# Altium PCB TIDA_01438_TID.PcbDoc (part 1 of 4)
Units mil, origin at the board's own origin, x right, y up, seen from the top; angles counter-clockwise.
Board outline 6250 x 2150 mil, 4 copper layers (Top Layer, V-, V+, Bottom Layer), stack 61.6 mil thick; 360 components, 217 nets, 1141 pads, 401 vias.
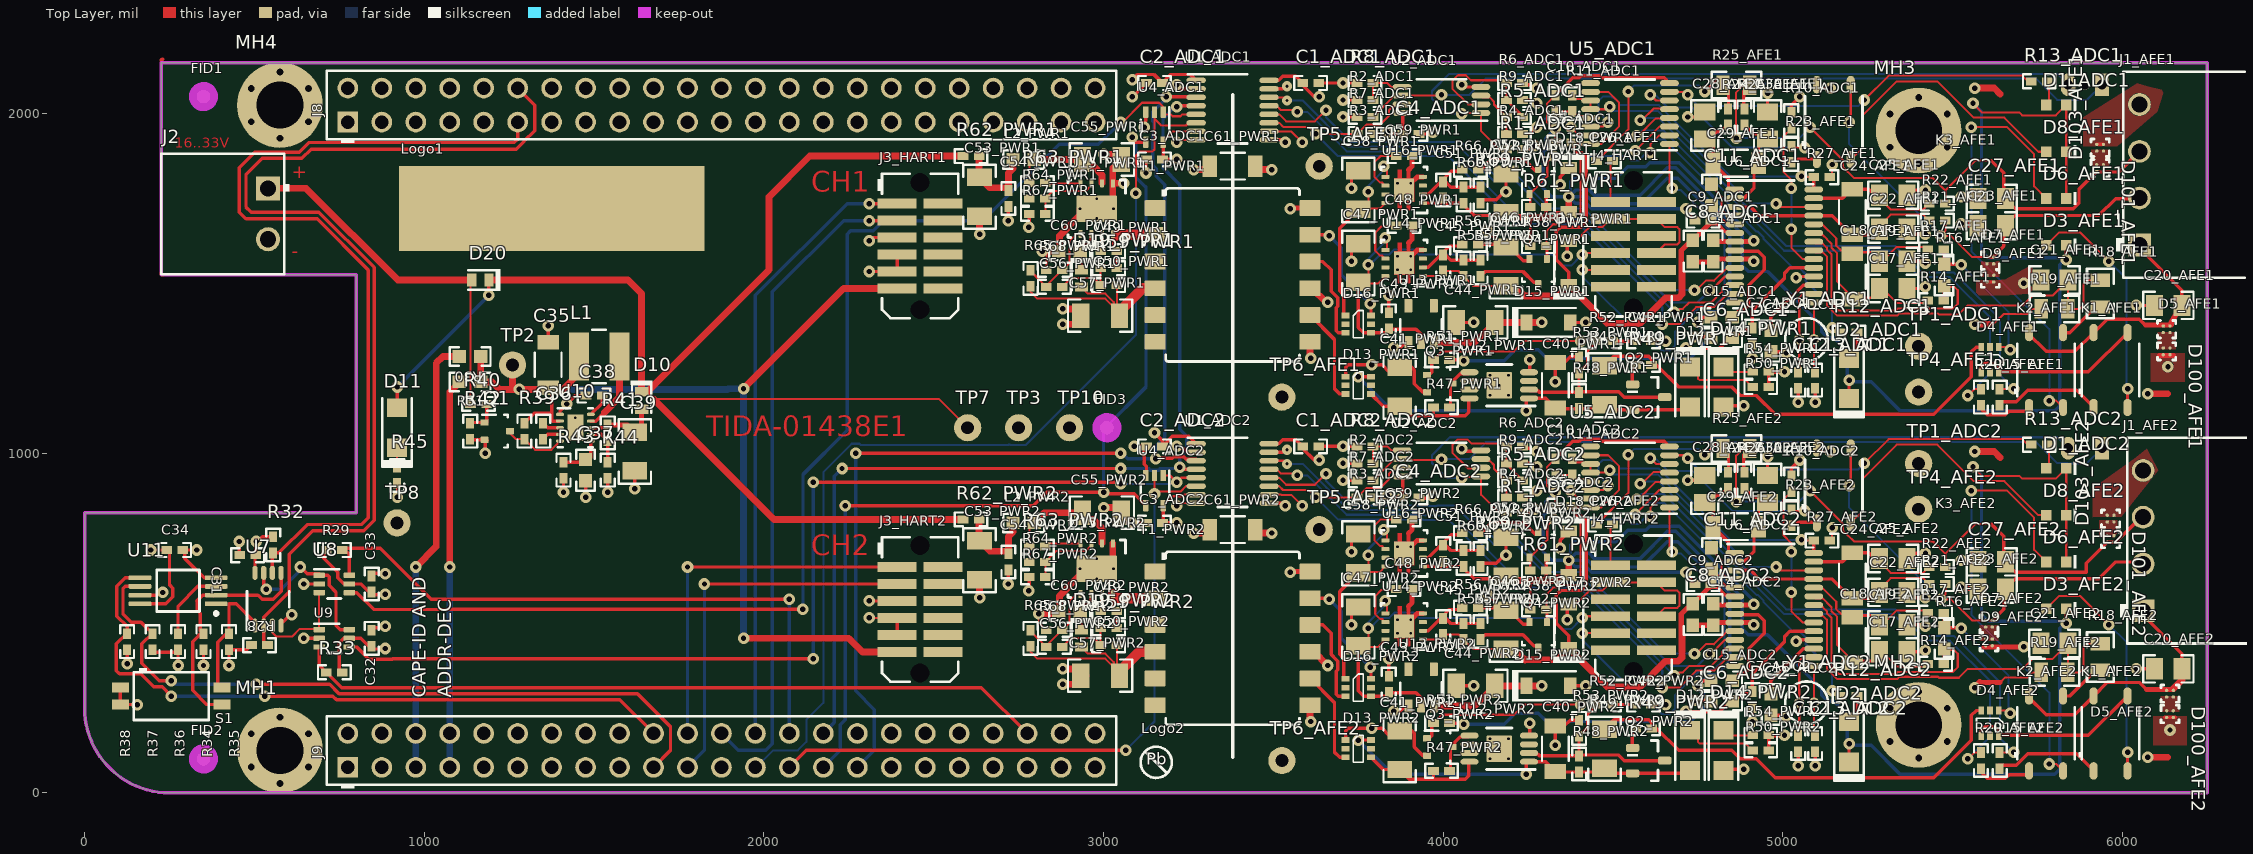
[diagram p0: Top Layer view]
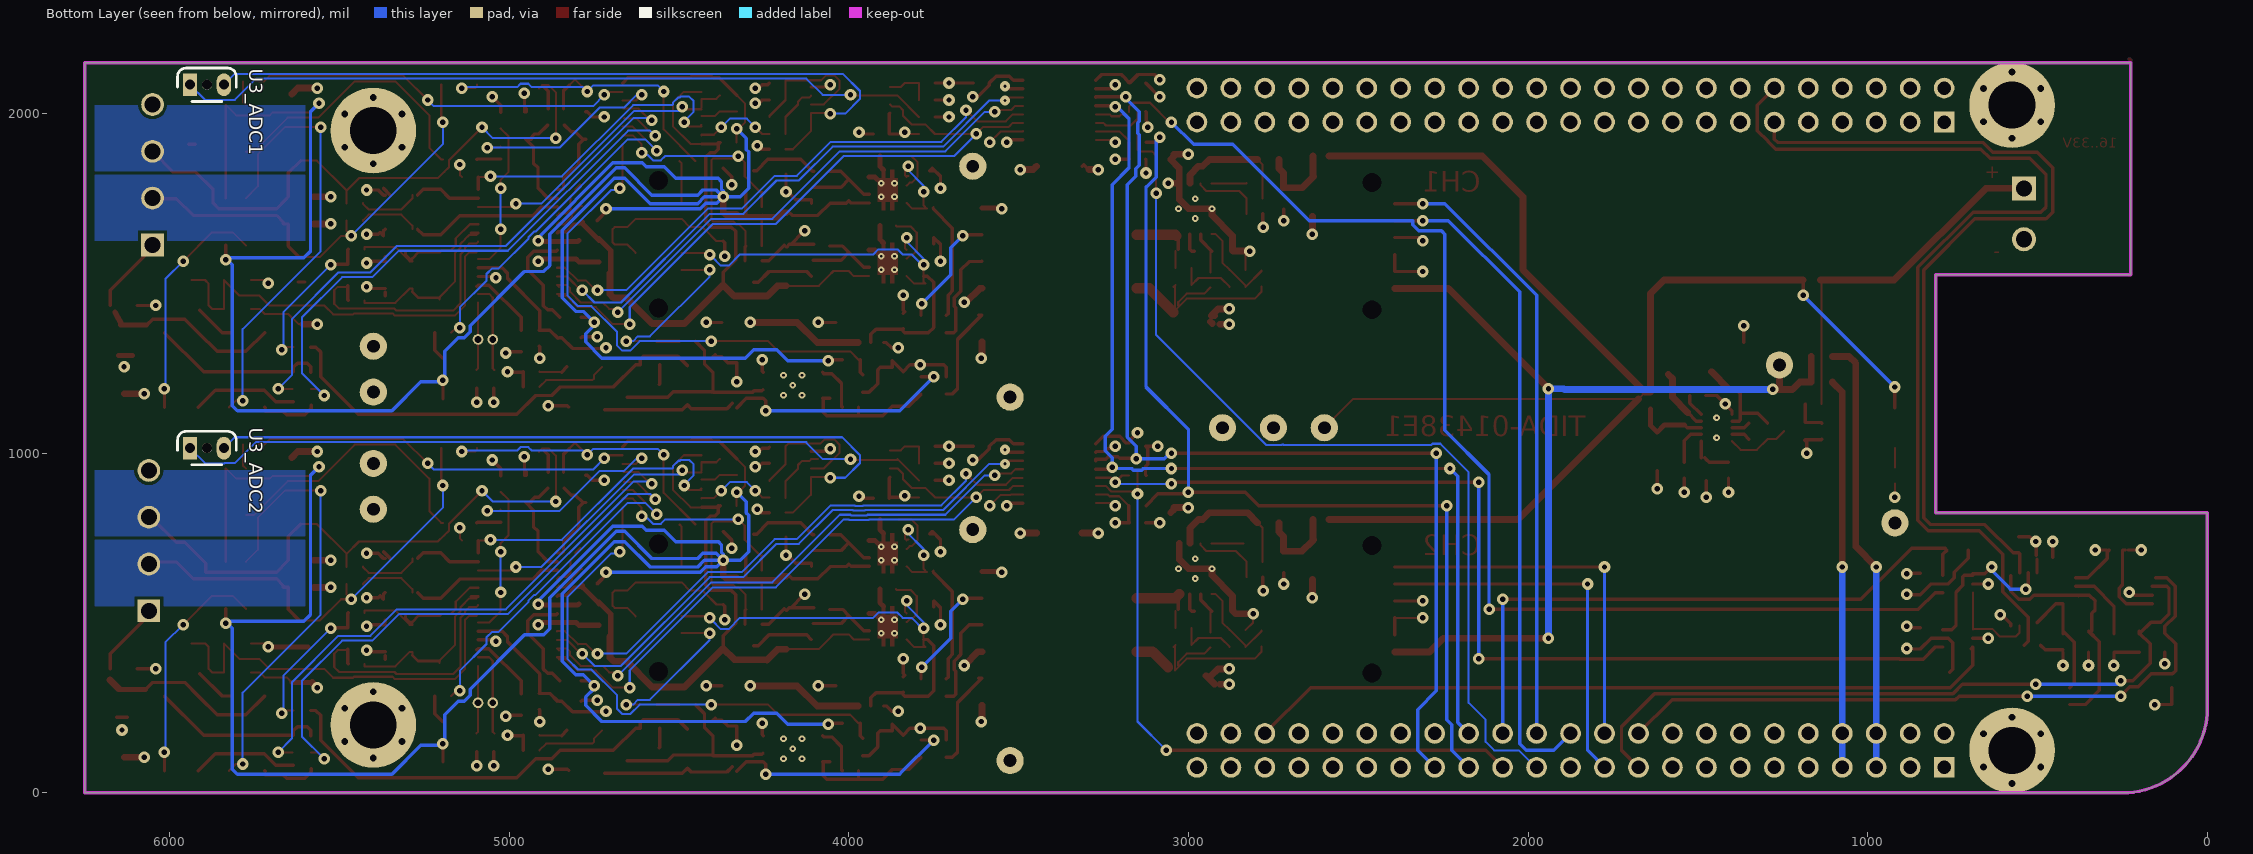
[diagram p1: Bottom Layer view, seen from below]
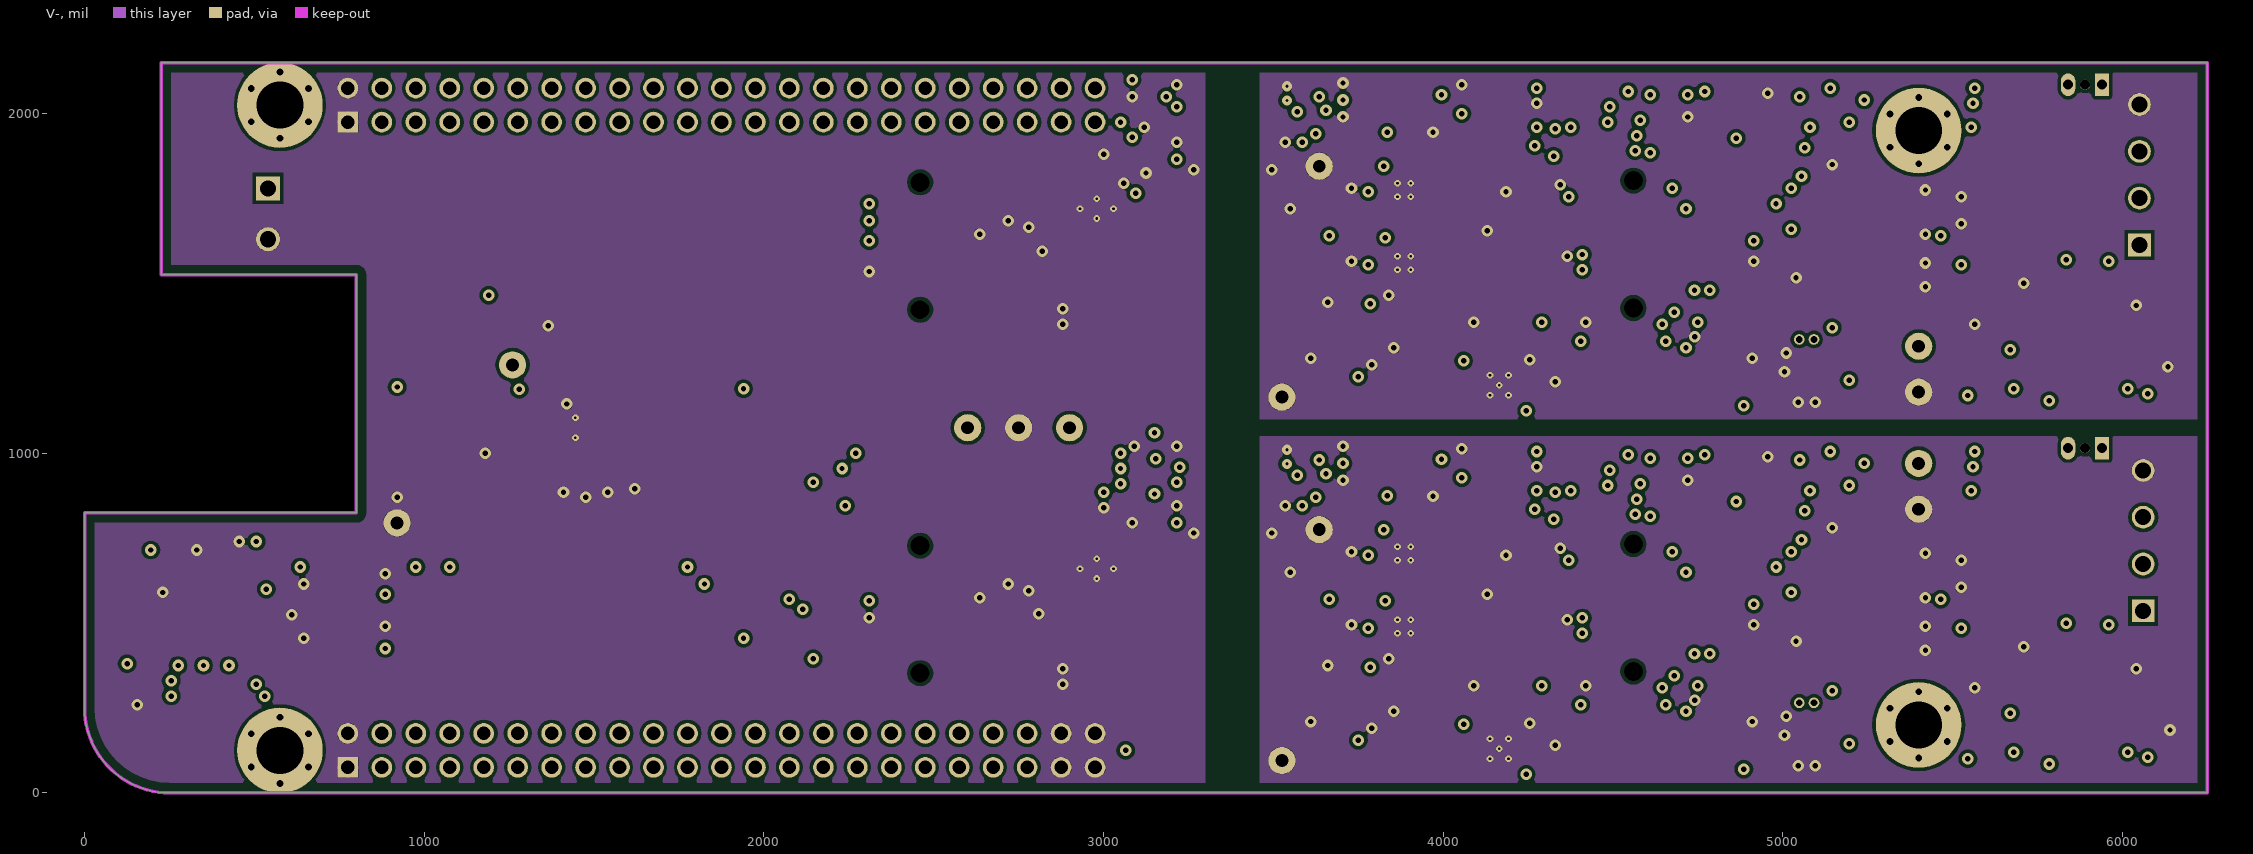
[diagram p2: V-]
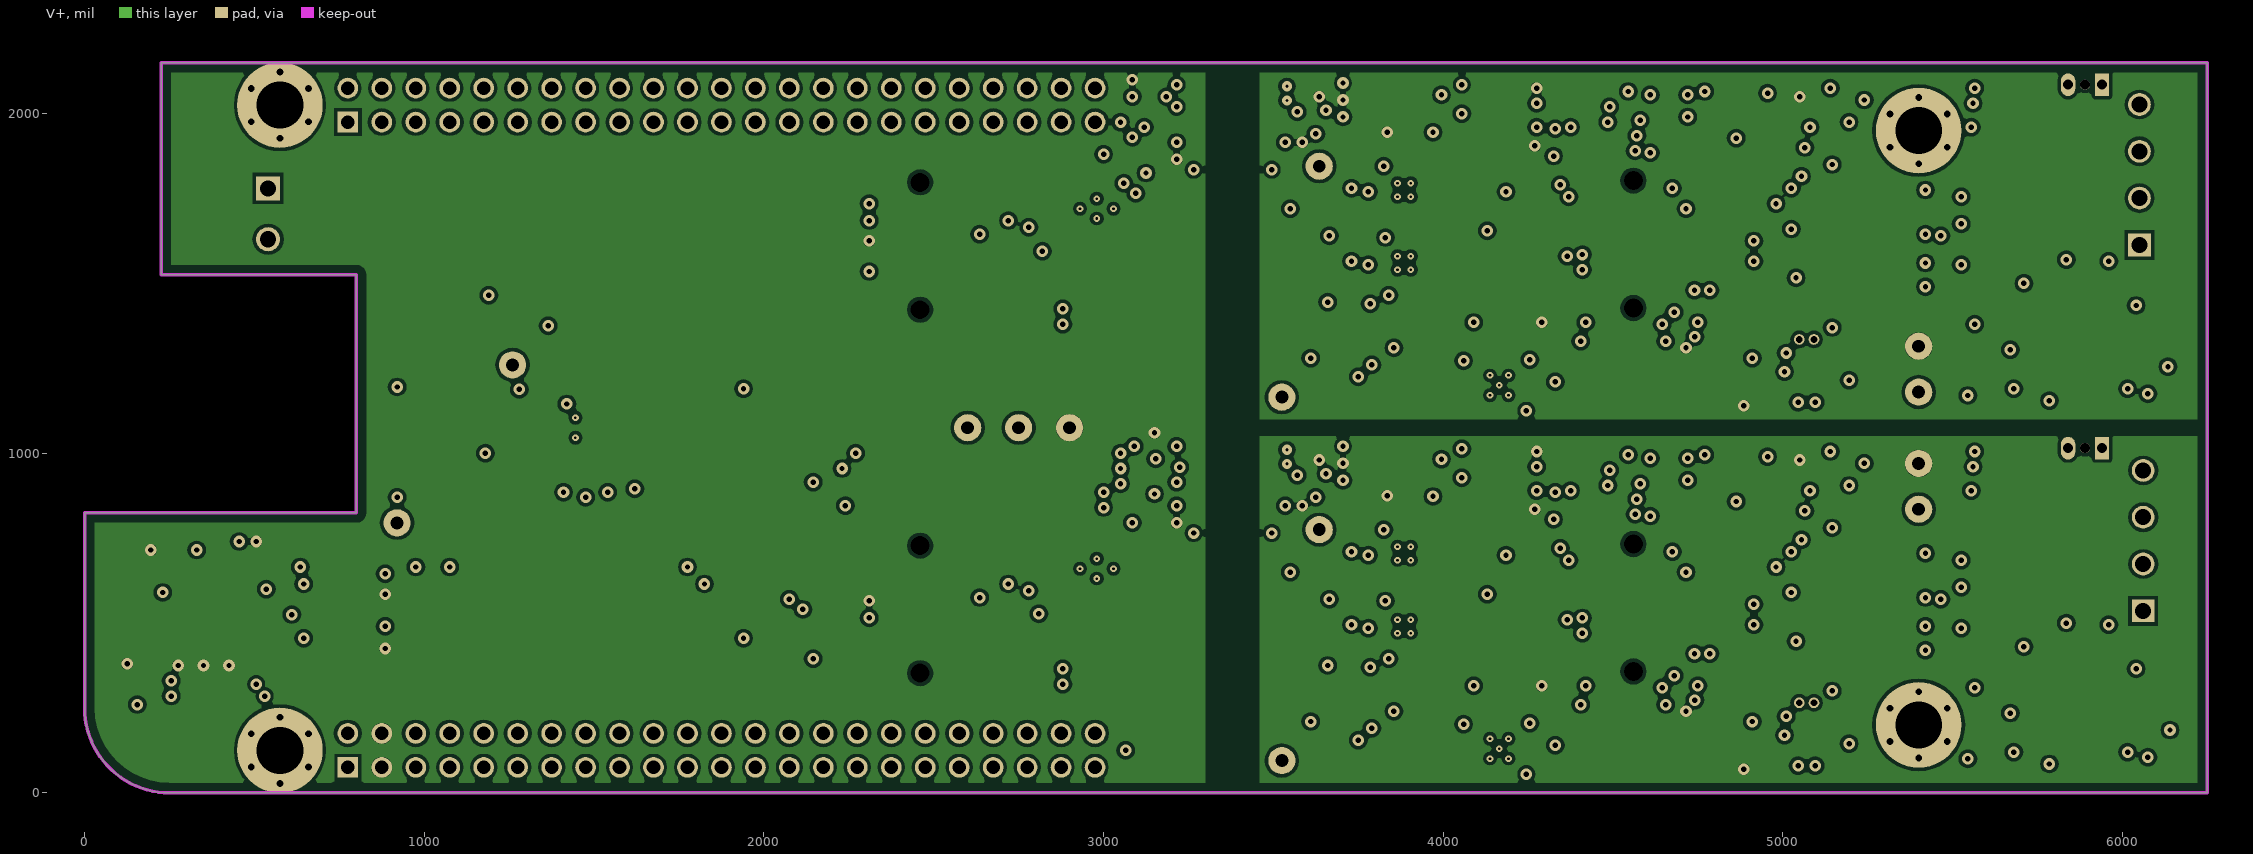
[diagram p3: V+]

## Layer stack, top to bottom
Top Solder: solder mask 0.4, Solder Resist, Dk 3.5
Top Layer: signal copper 1.4
Dielectric 1: core 8, Dk 4.2
V-: signal copper 1.4
Dielectric 2: prepreg 40, FR-4, Dk 4.2
V+: signal copper 1.4
Dielectric 3: core 8, Dk 4.2
Bottom Layer: signal copper 1.4
Bottom Solder: solder mask 0.4, Solder Resist, Dk 3.5

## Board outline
0,250 0,825 800,825 800,1525 225,1525 225,2150 6250,2150 6250,0 250,0 cw(c250,250)

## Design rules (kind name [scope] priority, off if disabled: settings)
AcuteAngle [All] p1: minimum=4.50000000000000E+0001 checktracksonly=FALSE
AssemblyTestPointUsage [All] p1: valid=2
Clearance Clearance_Keepouts [((IsTrack Or IsArc) And Not InPoly) And IsFree and IsKeepOut vs ((IsTrack Or IsArc) And Not InPoly) And IsFree and IsKeepOut] p1: gap=0
Clearance Clearance_BoardEdge_MountingHoles [OnCopper and InComponentClass('Mounting Holes') vs IsKeepOut] p2: gap=40
Clearance Clearance_BoardEdge_Poly [OnCopper and InPoly vs IsKeepOut] p3: gap=25
Clearance Clearance_BoardEdge [OnCopper and Not InComponentClass('Logo') and not InComponentClass('FiducialMark') and not InRegion(1000,500,4000,800) and Not IsKeepout vs IsKeepOut] p4: gap=25
Clearance Clearance_Poly [InPolygon] p5: gap=10
Clearance [All] p6: gap=7.87
ComponentClearance ComponentClearance_Standoff [InComponentClass('U_TIDA_01438_TID_Hardware')] p1: gap=0 collisioncheckmode=3 verticalgap=0 showdistances=FALSE
ComponentClearance ComponentClearance_J2 [InComponent('J2')] p2: gap=0 collisioncheckmode=3 verticalgap=0 showdistances=FALSE
ComponentClearance ComponentClearance_MountingHoles_FiducialMarks [InComponentClass('Mounting Holes') vs InComponentClass('FiducialMark')] p3: gap=50 collisioncheckmode=3 verticalgap=10 showdistances=FALSE
ComponentClearance ComponentClearance_Shunt [InComponentClass('Header') vs InComponentClass('Shunt')] p4: gap=0 collisioncheckmode=3 verticalgap=0 showdistances=FALSE
ComponentClearance ComponentClearance_Logo [InComponentClass('Logo')] p5: gap=50 collisioncheckmode=3 verticalgap=10 showdistances=FALSE
ComponentClearance ComponentClearance_ScrewToNut [(HasFootprint('NY PMS 440 0025 PH')) vs (HasFootprint('Keystone_1902C'))] p6: gap=5 collisioncheckmode=3 verticalgap=10 showdistances=FALSE
ComponentClearance ComponentClearance_MountingHoles [InComponentClass('Mounting Holes')] p7: gap=250 collisioncheckmode=3 verticalgap=100000 showdistances=FALSE
ComponentClearance ComponentClearance_SmallPassives [HasFootprint('0201*') or HasFootprint('0402*') or HasFootprint('0508') or HasFootprint('0603*') or HasFootprint('0612') or HasFootprint('0805*') or HasFootprint('0815*') or HasFootprint('0830*') or HasFootprint('1206*') or HasFootprint('1210*') or HasFootprint('1808*') or HasFootprint('1812*') or HasFootprint('1825*') or HasFootprint('2010*') or HasFootprint('2220*') or HasFootprint('2225*') or HasFootprint('2512*') or HasFootprint('2728*') or HasFootprint('3518*') vs HasFootprint('0201*') or HasFootprint('0402*') or HasFootprint('0508') or HasFootprint('0603*') or HasFootprint('0612') or HasFootprint('0805*') or HasFootprint('0815*') or HasFootprint('0830*') or HasFootprint('1206*') or HasFootprint('1210*') or HasFootprint('1808*') or HasFootprint('1812*') or HasFootprint('1825*') or HasFootprint('2010*') or HasFootprint('2220*') or HasFootprint('2225*') or HasFootprint('2512*') or HasFootprint('2728*') or HasFootprint('3518*')] p8: gap=20 collisioncheckmode=3 verticalgap=10 showdistances=FALSE
ComponentClearance ComponentClearance_THtoSMT [IsThruComponent vs IsSMTComponent] p9: gap=20 collisioncheckmode=3 verticalgap=30 showdistances=FALSE
ComponentClearance ComponentClearance_THtoTH [IsThruComponent vs IsThruComponent] p10: gap=50 collisioncheckmode=3 verticalgap=20 showdistances=FALSE
ComponentClearance [All] p11: gap=10 collisioncheckmode=3 verticalgap=10 showdistances=FALSE
DiffPairsRouting [All] p1: maxlimit=100 minlimit=10 mostfreqgap=10 toplayer_minwidth=15 toplayer_maxwidth=15 toplayer_prefwidth=15 midlayer1_minwidth=15 midlayer1_maxwidth=15 midlayer1_prefwidth=15 midlayer2_minwidth=15 midlayer2_maxwidth=15 midlayer2_prefwidth=15 bottomlayer_minwidth=15 bottomlayer_maxwidth=15 bottomlayer_prefwidth=15 maxuncoupledlength=1000
FabricationTestPointUsage TestPointUsage [All] p1: valid=2 allowmultiple=FALSE
FabricationTestpoint Testpoint [All] p1: side=3 testpointundercomponent=TRUE minsize=40 maxsize=100 preferedsize=60 minholesize=0 maxholesize=40 preferedholesize=32 testpointgrid=1 allowsidetop=TRUE allowsidebottom=TRUE usegrid=TRUE gridtolerance=0.01
FanoutControl Fanout_LCC [IsLCC] p1: bgadir=Out bgaviamode=Centered fanoutstyle=Auto fanoutdirection=Alternating viagrid=1 // Fanout_LCC (Default Rule)
FanoutControl Fanout_BGA [IsBGA] p2: bgadir=Out bgaviamode=Centered fanoutstyle=Auto fanoutdirection=Alternating viagrid=1 // Fanout_BGA (Default Rule)
FanoutControl Fanout_Default [All] p4: bgadir=Out bgaviamode=Centered fanoutstyle=Auto fanoutdirection=Alternating viagrid=1 // Fanout_Default (Default Rule)
FanoutControl Fanout_Small [(CompPinCount < 5)] p5: bgadir=Out bgaviamode=Centered fanoutstyle=Auto fanoutdirection=OutThenIn viagrid=1 // Fanout_Small (Default Rule)
HoleSize [All] p1: absolutevalues=TRUE maxlimit=251 minlimit=7 maxpercent=80.000 minpercent=20.000
MinimumAnnularRing MinimumAnnularRing_ThermalPadVias [IsVia and InAnyComponent] p1: minimumring=5.91
MinimumAnnularRing [All] p2: minimumring=5
MinimumSolderMaskSliver MinimumSolderMaskSliver_Logo [InComponentClass('Logo') vs InComponentClass('Logo')] p1: minsoldermaskwidth=0.7
MinimumSolderMaskSliver [All] p2: minsoldermaskwidth=3.94
PlaneConnect [All] p1: planeconnectstyle=Direct reliefexpansion=10 reliefentries=4 reliefconductorwidth=10 reliefairgap=10
PolygonConnect PolygonConnect_TVS3300 [HasFootprint('YZF0004-C01')] p1: connectstyle=Direct reliefconductorwidth=10 reliefentries=4 polygonreliefangle="90 Angle" airgapwidth=10
PolygonConnect PolygonConnect_12 [All vs IsNamedPolygon('GND_CH1_AVDD')] p2: connectstyle=Direct reliefconductorwidth=10 reliefentries=4 polygonreliefangle="90 Angle" airgapwidth=10
PolygonConnect PolygonConnect_11 [All vs IsNamedPolygon('GND_CH1_AVSS')] p3: connectstyle=Direct reliefconductorwidth=10 reliefentries=4 polygonreliefangle="90 Angle" airgapwidth=10
PolygonConnect PolygonConnect_10 [All vs IsNamedPolygon('LOCALTEMP_CH2_P')] p4: connectstyle=Direct reliefconductorwidth=10 reliefentries=4 polygonreliefangle="90 Angle" airgapwidth=10
PolygonConnect PolygonConnect_9 [All vs IsNamedPolygon('LOCALTEMP_CH1_P')] p5: connectstyle=Direct reliefconductorwidth=10 reliefentries=4 polygonreliefangle="90 Angle" airgapwidth=10
PolygonConnect PolygonConnect_8 [All vs IsNamedPolygon('LOCALTEMP_CH1_N')] p6: connectstyle=Direct reliefconductorwidth=10 reliefentries=4 polygonreliefangle="90 Angle" airgapwidth=10
PolygonConnect PolygonConnect_7 [All vs IsNamedPolygon('LOCALTEMP_CH2_N')] p7: connectstyle=Direct reliefconductorwidth=10 reliefentries=4 polygonreliefangle="90 Angle" airgapwidth=10
PolygonConnect PolygonConnect_6 [All vs IsNamedPolygon('LOCALTEMP_N')] p8: connectstyle=Direct reliefconductorwidth=10 reliefentries=4 polygonreliefangle="90 Angle" airgapwidth=10
PolygonConnect PolygonConnect_5 [All vs IsNamedPolygon('LOCALTEMP_P')] p9: connectstyle=Direct reliefconductorwidth=10 reliefentries=4 polygonreliefangle="90 Angle" airgapwidth=10
PolygonConnect PolygonConnect_4 [All vs IsNamedPolygon('LOCALTEMP_N')] p10: connectstyle=Direct reliefconductorwidth=10 reliefentries=4 polygonreliefangle="90 Angle" airgapwidth=10
PolygonConnect PolygonConnect_3 [All vs IsNamedPolygon('V--No Net')] p11: connectstyle=Relief reliefconductorwidth=10 reliefentries=4 polygonreliefangle="90 Angle" airgapwidth=10
PolygonConnect PolygonConnect_2 [All vs IsNamedPolygon('Bottom Layer-GND')] p12: connectstyle=Direct reliefconductorwidth=10 reliefentries=4 polygonreliefangle="90 Angle" airgapwidth=10
PolygonConnect PolygonConnect_1 [All vs IsNamedPolygon('Top Layer-No Net')] p13: connectstyle=Relief reliefconductorwidth=10 reliefentries=4 polygonreliefangle="90 Angle" airgapwidth=10
PolygonConnect [All vs IsNamedPolygon('Top Layer-VCC')] p14: connectstyle=Relief reliefconductorwidth=10 reliefentries=4 polygonreliefangle="90 Angle" airgapwidth=10
RoutingVias RoutingVias_Standoff [InNet('No Net')] p1: holewidth=28 width=50 viastyle="Through Hole" minholewidth=0 minwidth=0 maxholewidth=28 maxwidth=50
RoutingVias ThermalPadVias [IsVia and InAnyComponent] p2: holewidth=7.87 width=19.68 viastyle="Through Hole" minholewidth=7.87 minwidth=10 maxholewidth=50 maxwidth=50
RoutingVias [All] p3 off: holewidth=16 width=34 viastyle="Through Hole" minholewidth=7.87 minwidth=26 maxholewidth=40 maxwidth=65
ShortCircuit ShortCircuit_Standoff [IsVia vs IsPad] p1: allowed=TRUE
ShortCircuit [Not IsVia vs Not  IsPad] p2: allowed=FALSE
SilkToBoardRegionClearance [Not ((IsComment or IsDesignator) And (Hide <> 'False')) and not InRegion(1000,500,4000,800)] p1 off:
SilkToSilkClearance SilkToSilkClearance_Pb-FreeLogo [(HasFootprint('Pb-Free_Overlay_Medium') OR HasFootprint('Pb-Free_Overlay_Small')) vs (HasFootprint('Pb-Free_Overlay_Medium') OR HasFootprint('Pb-Free_Overlay_Small'))] p1 off: silktosilkclearance=0
SilkToSilkClearance [All] p2 off: silktosilkclearance=5
SilkToSolderMaskClearance "Silk to Solder Mask Opening" [All] p1 off: minsilkscreentomaskgap=1 clearancetoexposedcopper=FALSE
SolderMaskExpansion [All] p1: expansion=1.97
Width [All] p1: maxlimit=100 minlimit=6 preferedwidth=10 checkconnectedcopper=TRUE
14 further rules are at their usual default settings.

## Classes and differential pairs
channel class TIDA_01438_TID_Power: PWR1 PWR2
channel class TIDA_01438_TID_HART: HART1 HART2
channel class TIDA_01438_TID_Channel: CH1 CH2
channel class TIDA_01438_TID_AFE: AFE1 AFE2
channel class TIDA_01438_TID_ADS1262: ADC1 ADC2
net class LMT01_OUT[1..2]: LMT01_OUT1 LMT01_OUT2
net class UART_TXD[1..2]: UART_TXD1 UART_TXD2
net class UART_RXD[1..2]: UART_RXD1 UART_RXD2
net class SPI_CS[1..2]: SPI_CS1 SPI_CS2
component class U_TIDA_01438_TID_Hardware: FID1 FID2 FID3 Logo1 Logo2 MH1 MH2 MH3 MH4 ZZ1 ZZ2 ZZ3
component class Logo: Logo1
component class HART2: J3_HART2 J4_HART2
component class HART1: J3_HART1 J4_HART1
component class FiducialMark: FID1 FID2 FID3
component class AssemblyNote: ZZ1 ZZ2 ZZ3
component class TIDA_01438_TID_Cape: C31 C32 C33 C34 C35 C36 C37 C38 C39 D10 D11 D20 J2 J8 J9 L1 Q1 R28 R29 R30 R31 R32 R33 R34 R35 R36 R37 R38 R39 R40 R41 R42 R43 R44 R45 S1 TP2 TP3 TP7 TP8 TP10 U7 U8 U9 U10 U11
component class ADC1: C1_ADC1 C2_ADC1 C3_ADC1 C4_ADC1 C5_ADC1 C6_ADC1 C7_ADC1 C8_ADC1 C9_ADC1 C10_ADC1 C11_ADC1 C12_ADC1 C13_ADC1 C14_ADC1 C15_ADC1 C16_ADC1 D1_ADC1 D2_ADC1 R1_ADC1 R2_ADC1 R3_ADC1 R4_ADC1 R5_ADC1 R6_ADC1 R7_ADC1 R8_ADC1 R9_ADC1 R10_ADC1 R11_ADC1 R12_ADC1 R13_ADC1 TP1_ADC1 U1_ADC1 U2_ADC1 U3_ADC1 U4_ADC1 U5_ADC1 U6_ADC1 Y1_ADC1
component class ADC2: C1_ADC2 C2_ADC2 C3_ADC2 C4_ADC2 C5_ADC2 C6_ADC2 C7_ADC2 C8_ADC2 C9_ADC2 C10_ADC2 C11_ADC2 C12_ADC2 C13_ADC2 C14_ADC2 C15_ADC2 C16_ADC2 D1_ADC2 D2_ADC2 R1_ADC2 R2_ADC2 R3_ADC2 R4_ADC2 R5_ADC2 R6_ADC2 R7_ADC2 R8_ADC2 R9_ADC2 R10_ADC2 R11_ADC2 R12_ADC2 R13_ADC2 TP1_ADC2 U1_ADC2 U2_ADC2 U3_ADC2 U4_ADC2 U5_ADC2 U6_ADC2 Y1_ADC2
component class AFE1: C17_AFE1 C18_AFE1 C19_AFE1 C20_AFE1 C21_AFE1 C22_AFE1 C23_AFE1 C24_AFE1 C25_AFE1 C26_AFE1 C27_AFE1 C28_AFE1 C29_AFE1 C30_AFE1 D3_AFE1 D4_AFE1 D5_AFE1 D6_AFE1 D7_AFE1 D8_AFE1 D9_AFE1 D100_AFE1 D101_AFE1 D103_AFE1 J1_AFE1 K1_AFE1 K2_AFE1 K3_AFE1 R14_AFE1 R15_AFE1 R16_AFE1 R17_AFE1 R18_AFE1 R19_AFE1 R20_AFE1 R21_AFE1 R22_AFE1 R23_AFE1 R24_AFE1 R25_AFE1 R26_AFE1 R27_AFE1 TP4_AFE1 TP5_AFE1 TP6_AFE1
component class AFE2: C17_AFE2 C18_AFE2 C19_AFE2 C20_AFE2 C21_AFE2 C22_AFE2 C23_AFE2 C24_AFE2 C25_AFE2 C26_AFE2 C27_AFE2 C28_AFE2 C29_AFE2 C30_AFE2 D3_AFE2 D4_AFE2 D5_AFE2 D6_AFE2 D7_AFE2 D8_AFE2 D9_AFE2 D100_AFE2 D101_AFE2 D103_AFE2 J1_AFE2 K1_AFE2 K2_AFE2 K3_AFE2 R14_AFE2 R15_AFE2 R16_AFE2 R17_AFE2 R18_AFE2 R19_AFE2 R20_AFE2 R21_AFE2 R22_AFE2 R23_AFE2 R24_AFE2 R25_AFE2 R26_AFE2 R27_AFE2 TP4_AFE2 TP5_AFE2 TP6_AFE2
component class PWR1: C40_PWR1 C41_PWR1 C42_PWR1 C43_PWR1 C44_PWR1 C45_PWR1 C46_PWR1 C47_PWR1 C48_PWR1 C49_PWR1 C50_PWR1 C51_PWR1 C52_PWR1 C53_PWR1 C54_PWR1 C55_PWR1 C56_PWR1 C57_PWR1 C58_PWR1 C59_PWR1 C60_PWR1 C61_PWR1 D12_PWR1 D13_PWR1 D14_PWR1 D15_PWR1 D16_PWR1 D17_PWR1 D18_PWR1 D19_PWR1 L2_PWR1 Q2_PWR1 Q3_PWR1 Q4_PWR1 Q5_PWR1 R46_PWR1 R47_PWR1 R48_PWR1 R49_PWR1 R50_PWR1 R51_PWR1 R52_PWR1 R53_PWR1 R54_PWR1 R55_PWR1 R56_PWR1 R57_PWR1 R58_PWR1 R59_PWR1 R60_PWR1 R61_PWR1 R62_PWR1 R63_PWR1 R64_PWR1 R65_PWR1 R66_PWR1 R67_PWR1 R68_PWR1 R69_PWR1 T1_PWR1 U12_PWR1 U13_PWR1 U14_PWR1 U15_PWR1 U16_PWR1
component class PWR2: C40_PWR2 C41_PWR2 C42_PWR2 C43_PWR2 C44_PWR2 C45_PWR2 C46_PWR2 C47_PWR2 C48_PWR2 C49_PWR2 C50_PWR2 C51_PWR2 C52_PWR2 C53_PWR2 C54_PWR2 C55_PWR2 C56_PWR2 C57_PWR2 C58_PWR2 C59_PWR2 C60_PWR2 C61_PWR2 D12_PWR2 D13_PWR2 D14_PWR2 D15_PWR2 D16_PWR2 D17_PWR2 D18_PWR2 D19_PWR2 L2_PWR2 Q2_PWR2 Q3_PWR2 Q4_PWR2 Q5_PWR2 R46_PWR2 R47_PWR2 R48_PWR2 R49_PWR2 R50_PWR2 R51_PWR2 R52_PWR2 R53_PWR2 R54_PWR2 R55_PWR2 R56_PWR2 R57_PWR2 R58_PWR2 R59_PWR2 R60_PWR2 R61_PWR2 R62_PWR2 R63_PWR2 R64_PWR2 R65_PWR2 R66_PWR2 R67_PWR2 R68_PWR2 R69_PWR2 T1_PWR2 U12_PWR2 U13_PWR2 U14_PWR2 U15_PWR2 U16_PWR2

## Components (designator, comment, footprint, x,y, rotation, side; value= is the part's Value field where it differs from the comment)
C1_ADC1 "C1005X7R1H104K" 0402 3610,2090 r0 top (schematic designator C1)
C1_ADC2 "C1005X7R1H104K" 0402 3610,1020 r0 top (schematic designator C1)
C2_ADC1 "C1005X7R1H104K" 0402 3150,2090 r180 top (schematic designator C2)
C2_ADC2 "C1005X7R1H104K" 0402 3150,1020 r180 top (schematic designator C2)
C3_ADC1 "C1005X7R1H104K" 0402 3150,1865 r180 top (schematic designator C3)
C3_ADC2 "C1005X7R1H104K" 0402 3150,795 r180 top (schematic designator C3)
C4_ADC1 "C1005X7R1H104K" 0402 3905,1940 r0 top (schematic designator C4)
C4_ADC2 "C1005X7R1H104K" 0402 3905,870 r0 top (schematic designator C4)
C5_ADC1 "C1005X7R1H104K" 0402 4355,1915 r180 top (schematic designator C5)
C5_ADC2 "C1005X7R1H104K" 0402 4355,845 r180 top (schematic designator C5)
C6_ADC1 "C1608X7R1C105K" 0603 4820,1340 r180 top (schematic designator C6)
C6_ADC2 "C1608X7R1C105K" 0603 4820,270 r180 top (schematic designator C6)
C7_ADC1 "C1005X7R1H104K" 0402 4910,1345 r270 top (schematic designator C7)
C7_ADC2 "C1005X7R1H104K" 0402 4910,275 r270 top (schematic designator C7)
C8_ADC1 "C1608X7R1C105K" 0603 4735,1595 r270 top (schematic designator C8)
C8_ADC2 "C1608X7R1C105K" 0603 4735,525 r270 top (schematic designator C8)
C9_ADC1 "C1005X7R1H104K" 0402 4765,1685 r180 top (schematic designator C9)
C9_ADC2 "C1005X7R1H104K" 0402 4765,615 r180 top (schematic designator C9)
C10_ADC1 "C1005X7R1H104K" 0402 4330,2030 r90 top (schematic designator C10)
C10_ADC2 "C1005X7R1H104K" 0402 4330,960 r90 top (schematic designator C10)
C11_ADC1 "C1608C0G1E472J" 0603 4790,1760 r270 top (schematic designator C11)
C11_ADC2 "C1608C0G1E472J" 0603 4790,690 r270 top (schematic designator C11)
C12_ADC1 "GRM1555C1E330JA01D" 0402 5045,1215 r270 top (schematic designator C12)
C12_ADC2 "GRM1555C1E330JA01D" 0402 5045,145 r270 top (schematic designator C12)
C13_ADC1 "GRM1555C1E330JA01D" 0402 5095,1215 r270 top (schematic designator C13)
C13_ADC2 "GRM1555C1E330JA01D" 0402 5095,145 r270 top (schematic designator C13)
C14_ADC1 "C1608X7R1C105K" 0603 4795,1595 r270 top (schematic designator C14)
C14_ADC2 "C1608X7R1C105K" 0603 4795,525 r270 top (schematic designator C14)
C15_ADC1 "C1608X7R1C105K" 0603 4820,1400 r180 top (schematic designator C15)
C15_ADC2 "C1608X7R1C105K" 0603 4820,330 r180 top (schematic designator C15)
C16_ADC1 "C1608X7R1C105K" 0603 4965,1330 r270 top (schematic designator C16)
C16_ADC2 "C1608X7R1C105K" 0603 4965,260 r270 top (schematic designator C16)
C17_AFE1 "GRM2195C1H822JA01D" 0805_HV 5325,1485 r0 top (schematic designator C17)
C17_AFE2 "GRM2195C1H822JA01D" 0805_HV 5325,415 r0 top (schematic designator C17)
C18_AFE1 "C3216NP01H104J160AA" 1206_190 5205,1520 r90 top (schematic designator C18)
C18_AFE2 "C3216NP01H104J160AA" 1206_190 5205,450 r90 top (schematic designator C18)
C19_AFE1 "GRM2195C1H822JA01D" 0805_HV 5325,1565 r180 top (schematic designator C19)
C19_AFE2 "GRM2195C1H822JA01D" 0805_HV 5325,495 r180 top (schematic designator C19)
C20_AFE1 "08051C103KAT2A" 0805_HV 6135,1435 r180 top (schematic designator C20)
C20_AFE2 "08051C103KAT2A" 0805_HV 6135,365 r180 top (schematic designator C20)
C21_AFE1 "GRM2195C1H562JA01D" 0805_HV 5800,1510 r180 top (schematic designator C21)
C21_AFE2 "GRM2195C1H562JA01D" 0805_HV 5800,440 r180 top (schematic designator C21)
C22_AFE1 "GRM2195C1H822JA01D" 0805_HV 5325,1660 r0 top (schematic designator C22)
C22_AFE2 "GRM2195C1H822JA01D" 0805_HV 5325,590 r0 top (schematic designator C22)
C23_AFE1 "08051C103KAT2A" 0805_HV 5615,1670 r180 top (schematic designator C23)
C23_AFE2 "08051C103KAT2A" 0805_HV 5615,600 r180 top (schematic designator C23)
C24_AFE1 "C3216NP01H104J160AA" 1206_190 5205,1710 r90 top (schematic designator C24)
C24_AFE2 "C3216NP01H104J160AA" 1206_190 5205,640 r90 top (schematic designator C24)
C25_AFE1 "GRM2195C1H822JA01D" 0805_HV 5325,1760 r180 top (schematic designator C25)
C25_AFE2 "GRM2195C1H822JA01D" 0805_HV 5325,690 r180 top (schematic designator C25)
C26_AFE1 "C1005X7R1H104K" 0402 4475,1860 r0 top (schematic designator C26)
C26_AFE2 "C1005X7R1H104K" 0402 4475,790 r0 top (schematic designator C26)
C27_AFE1 "08051C103KAT2A" 0805_HV 5615,1750 r180 top (schematic designator C27)
C27_AFE2 "08051C103KAT2A" 0805_HV 5615,680 r180 top (schematic designator C27)
C28_AFE1 "GRM2195C1H822JA01D" 0805_HV 4770,1965 r90 top (schematic designator C28)
C28_AFE2 "GRM2195C1H822JA01D" 0805_HV 4770,895 r90 top (schematic designator C28)
C29_AFE1 "C3216NP01H104J160AA" 1206_190 4861.57,1853.77 r0 top (schematic designator C29)
C29_AFE2 "C3216NP01H104J160AA" 1206_190 4861.57,783.77 r0 top (schematic designator C29)
C30_AFE1 "GRM2195C1H822JA01D" 0805_HV 4955,1965 r270 top (schematic designator C30)
C30_AFE2 "GRM2195C1H822JA01D" 0805_HV 4955,895 r270 top (schematic designator C30)
C31 "C1005X7R1H104K" 0402 480,700 r180 top
C32 "C1005X7R1H104K" 0402 845.02,455.02 r90 top
C33 "C1005X7R1H104K" 0402 845.02,615.01 r90 top
C34 "C1005X7R1H104K" 0402 265.01,715.01 r0 top
C35 "C3216X7R1H475M160AC" 1206_190 1365,1260 r90 top
C36 "C1005X7R1H104K" 0402 1350,1065 r90 top
C37 "C1608X7R1C105K" 0603 1475,950 r270 top
C38 "C1005X7R1H104K" 0402 1500,1170 r180 top
C39 "UMK316B7225KL-T" 1206 1620,1005 r270 top
C40_PWR1 "C3216X7R1H475M160AC" 1206_190 4330,1200 r90 top (schematic designator C40)
C40_PWR2 "C3216X7R1H475M160AC" 1206_190 4330,130 r90 top (schematic designator C40)
C41_PWR1 "UMK316B7225KL-T" 1206 3871.86,1195.81 r90 top (schematic designator C41)
C41_PWR2 "UMK316B7225KL-T" 1206 3871.86,125.81 r90 top (schematic designator C41)
C42_PWR1 "GRM155R71H271KA01D" 0402 4590,1330 r0 top (schematic designator C42)
C42_PWR2 "GRM155R71H271KA01D" 0402 4590,260 r0 top (schematic designator C42)
C43_PWR1 "C1005X7R1H104K" 0402 3840,1390 r90 top (schematic designator C43)
C43_PWR2 "C1005X7R1H104K" 0402 3840,320 r90 top (schematic designator C43)
C44_PWR1 "C3216X7R1C106M" 1206 4095,1385 r180 top (schematic designator C44)
C44_PWR2 "C3216X7R1C106M" 1206 4095,315 r180 top (schematic designator C44)
C45_PWR1 "GRM155R71E103KA01D" 0402 4000,1560 r90 top (schematic designator C45)
C45_PWR2 "GRM155R71E103KA01D" 0402 4000,490 r90 top (schematic designator C45)
C46_PWR1 "C3216X7R1C106M" 1206 4185,1550 r90 top (schematic designator C46)
C46_PWR2 "C3216X7R1C106M" 1206 4185,480 r90 top (schematic designator C46)
C47_PWR1 "C3216X7R1C106M" 1206 3750,1560 r90 top (schematic designator C47)
C47_PWR2 "C3216X7R1C106M" 1206 3750,490 r90 top (schematic designator C47)
C48_PWR1 "GRM155R71E103KA01D" 0402 3885,1670 r0 top (schematic designator C48)
C48_PWR2 "GRM155R71E103KA01D" 0402 3885,600 r0 top (schematic designator C48)
C49_PWR1 "GRM155R71E103KA01D" 0402 3015,1595 r180 top (schematic designator C49)
C49_PWR2 "GRM155R71E103KA01D" 0402 3015,535 r180 top (schematic designator C49)
C50_PWR1 "GRM155R71H332KA01D" 0402 3015,1495 r180 top (schematic designator C50)
C50_PWR2 "GRM155R71H332KA01D" 0402 3015,435 r180 top (schematic designator C50)
C51_PWR1 "GRM155R71E103KA01D" 0402 4000,1775 r90 top (schematic designator C51)
C51_PWR2 "GRM155R71E103KA01D" 0402 4000,705 r90 top (schematic designator C51)
C52_PWR1 "C3216X7R1C106M" 1206 4185,1765 r90 top (schematic designator C52)
C52_PWR2 "C3216X7R1C106M" 1206 4185,695 r90 top (schematic designator C52)
C53_PWR1 "UMK316B7225KL-T" 1206 2635,1755 r270 top (schematic designator C53)
C53_PWR2 "UMK316B7225KL-T" 1206 2635,685 r270 top (schematic designator C53)
C54_PWR1 "C1005X7R1H104K" 0402 2720,1750 r270 top (schematic designator C54)
C54_PWR2 "C1005X7R1H104K" 0402 2720,680 r270 top (schematic designator C54)
C55_PWR1 "UMK316B7225KL-T" 1206 2995,1865 r0 top (schematic designator C55)
C55_PWR2 "UMK316B7225KL-T" 1206 2995,825 r0 top (schematic designator C55)
C56_PWR1 "C1005X7R1H104K" 0402 2855,1490 r180 top (schematic designator C56)
C56_PWR2 "C1005X7R1H104K" 0402 2855,430 r180 top (schematic designator C56)
C57_PWR1 "GRM31CR71E106KA12L" 1206 2990,1405 r180 top (schematic designator C57)
C57_PWR2 "GRM31CR71E106KA12L" 1206 2990,345 r180 top (schematic designator C57)
C58_PWR1 "C3216X7R1C106M" 1206 3750,1775 r90 top (schematic designator C58)
C58_PWR2 "C3216X7R1C106M" 1206 3750,705 r90 top (schematic designator C58)
C59_PWR1 "GRM155R71E103KA01D" 0402 3885,1875 r0 top (schematic designator C59)
C59_PWR2 "GRM155R71E103KA01D" 0402 3885,805 r0 top (schematic designator C59)
C60_PWR1 "GRM188R71E105KA12D" 0603 2900,1595 r180 top (schematic designator C60)
C60_PWR2 "GRM188R71E105KA12D" 0603 2900,535 r180 top (schematic designator C60)
C61_PWR1 "202R18W102KV4E" 1206_190 3380.02,1845 r180 top (schematic designator C61)
C61_PWR2 "202R18W102KV4E" 1206_190 3380.02,775 r180 top (schematic designator C61)
D1_ADC1 "LB Q39G-L2N2-35-1" "LB Q39G_BLUE" 5805,2025.4 r0 top (schematic designator D1)
D1_ADC2 "LB Q39G-L2N2-35-1" "LB Q39G_BLUE" 5805,955.39 r0 top (schematic designator D1)
D2_ADC1 "150120RS75000" WL_SMCW_RED_1206 5195,1220 r90 top (schematic designator D2)
D2_ADC2 "150120RS75000" WL_SMCW_RED_1206 5195,150 r90 top (schematic designator D2)
D3_AFE1 "LB Q39G-L2N2-35-1" "LB Q39G_BLUE" 5805,1612.01 r0 top (schematic designator D3)
D3_AFE2 "LB Q39G-L2N2-35-1" "LB Q39G_BLUE" 5805,542.01 r0 top (schematic designator D3)
D4_AFE1 "BAS70JW-7-F" SOT-363 5610,1275 r270 top (schematic designator D4)
D4_AFE2 "BAS70JW-7-F" SOT-363 5610,205 r270 top (schematic designator D4)
D5_AFE1 "TVS3300YZFR" YZF0004-C01 6130,1365 r180 top (schematic designator D5)
D5_AFE2 "TVS3300YZFR" YZF0004-C01 6139.92,291.89 r180 top (schematic designator D5)
D6_AFE1 "LB Q39G-L2N2-35-1" "LB Q39G_BLUE" 5805,1750 r0 top (schematic designator D6)
D6_AFE2 "LB Q39G-L2N2-35-1" "LB Q39G_BLUE" 5805,679.97 r0 top (schematic designator D6)
D7_AFE1 "TVS3300YZFR" YZF0004-C01 5611,1567.48 r180 top (schematic designator D7)
D7_AFE2 "TVS3300YZFR" YZF0004-C01 5607,498 r180 top (schematic designator D7)
D8_AFE1 "LB Q39G-L2N2-35-1" "LB Q39G_BLUE" 5805,1887.6 r0 top (schematic designator D8)
D8_AFE2 "LB Q39G-L2N2-35-1" "LB Q39G_BLUE" 5805,817.56 r0 top (schematic designator D8)
D9_AFE1 "TVS3300YZFR" YZF0004-C01 5611,1514 r0 top (schematic designator D9)
D9_AFE2 "TVS3300YZFR" YZF0004-C01 5607,443 r0 top (schematic designator D9)
D10 "CD0603-B0230" Diode_0603 1640,1155 r270 top
D11 "150120VS75000" WL_SMCW_GREEN_1206 920,1075 r90 top
D12_PWR1 "150120VS75000" WL_SMCW_GREEN_1206 4726.5,1195 r270 top (schematic designator D12)
D12_PWR2 "150120VS75000" WL_SMCW_GREEN_1206 4726.5,125 r270 top (schematic designator D12)
D13_PWR1 "BAS70JW-7-F" SOT-363 3750,1200 r0 top (schematic designator D13)
D13_PWR2 "BAS70JW-7-F" SOT-363 3750,130 r0 top (schematic designator D13)
D14_PWR1 "150120VS75000" WL_SMCW_GREEN_1206 4825,1195 r270 top (schematic designator D14)
D14_PWR2 "150120VS75000" WL_SMCW_GREEN_1206 4825,125 r270 top (schematic designator D14)
D15_PWR1 "MMSZ4685-V" SOD-123 4310,1385 r0 top (schematic designator D15)
D15_PWR2 "MMSZ4685-V" SOD-123 4310,315 r0 top (schematic designator D15)
D16_PWR1 "BAS70JW-7-F" SOT-363 3750,1380 r0 top (schematic designator D16)
D16_PWR2 "BAS70JW-7-F" SOT-363 3750,310 r0 top (schematic designator D16)
D17_PWR1 "MMSZ4685-V" SOD-123 4370,1560 r90 top (schematic designator D17)
D17_PWR2 "MMSZ4685-V" SOD-123 4370,490.02 r90 top (schematic designator D17)
D18_PWR1 "MMSZ4682-V" SOD-123 4370,1775 r270 top (schematic designator D18)
D18_PWR2 "MMSZ4682-V" SOD-123 4370,705 r270 top (schematic designator D18)
D19_PWR1 "CD0603-B0230" Diode_0603 2935,1515 r270 top (schematic designator D19)
D19_PWR2 "CD0603-B0230" Diode_0603 2935,455 r270 top (schematic designator D19)
D20 "CD0603-B0230" Diode_0603 1165,1510 r180 top
D100_AFE1 "TVS3300YZFR" YZF0004-C01 6130,1300 r0 top (schematic designator D100)
D100_AFE2 "TVS3300YZFR" YZF0004-C01 6139.92,231.89 r0 top (schematic designator D100)
D101_AFE1 "TVS3300YZFR" YZF0004-C01 5934.11,1839.41 r0 top (schematic designator D101)
D101_AFE2 "TVS3300YZFR" YZF0004-C01 5965,747.48 r0 top (schematic designator D101)
D103_AFE1 "TVS3300YZFR" YZF0004-C01 5934.11,1899.41 r180 top (schematic designator D103)
D103_AFE2 "TVS3300YZFR" YZF0004-C01 5965,807.48 r180 top (schematic designator D103)
FID1 "Fiducial" Fiducial10-20 350,2050 r0 top
FID2 "Fiducial" Fiducial10-20 350,100 r0 top
FID3 "Fiducial" Fiducial10-20 3010,1075 r0 top
J1_AFE1 "1844236" Phoenix_1844236 6365,1820 r180 top (schematic designator J1)
J1_AFE2 "1844236" Phoenix_1844236 6376,742.7 r180 top (schematic designator J1)
J2 "1803277" PhoenixContact_1803277 540,1705 r270 top
J3_HART1 "TFM-106-02-S-D-A" Samtec_TFM-106-02-x-D-A 2460,1610 r0 top (schematic designator J3)
J3_HART2 "TFM-106-02-S-D-A" Samtec_TFM-106-02-x-D-A 2460,540 r0 top (schematic designator J3)
J4_HART1 "TFM-106-02-S-D-A" Samtec_TFM-106-02-x-D-A 4560,1615 r0 top (schematic designator J4)
J4_HART2 "TFM-106-02-S-D-A" Samtec_TFM-106-02-x-D-A 4560,545 r0 top (schematic designator J4)
J8 "SSHQ-123-D-08-F-LF" Major_BBB_SSHQ-123-D-08 1875,2025 r0 top locked
J9 "SSHQ-123-D-08-F-LF" Major_BBB_SSHQ-123-D-08 1875,125 r0 top locked
K1_AFE1 "CPC1017N" RELAY_CPC1017N 5965,1245 r90 top (schematic designator K1)
K1_AFE2 "CPC1017N" RELAY_CPC1017N 5965,175 r90 top (schematic designator K1)
K2_AFE1 "CPC1017N" RELAY_CPC1017N 5775,1245 r90 top (schematic designator K2)
K2_AFE2 "CPC1017N" RELAY_CPC1017N 5775,175 r90 top (schematic designator K2)
K3_AFE1 "CPC1017N" RELAY_CPC1017N 5150,1975 r90 top (schematic designator K3)
K3_AFE2 "CPC1017N" RELAY_CPC1017N 5150,905 r90 top (schematic designator K3)
L1 "74404042100" WE-LQS_4018 1515,1285 r0 top
L2_PWR1 "LQM18PN2R2MFH" 0603 2765,1865 r0 top (schematic designator L2)
L2_PWR2 "LQM18PN2R2MFH" 0603 2765,795 r0 top (schematic designator L2)
Logo1 "Texas Instruments" TI_Stacked_SolderMask_Small 1375,1720 r0 top
Logo2 "Pb-Free Symbol" Pb-Free_Overlay_Small 3155,90 r0 top
MH1 "MTG_Pads" MTGP_4-40_PanHead 575,125 r0 top locked
MH2 "MTG_Pads" MTGP_4-40_PanHead 5400,200 r0 top
MH3 "MTG_Pads" MTGP_4-40_PanHead 5400,1950 r0 top locked
MH4 "MTG_Pads" MTGP_4-40_PanHead 575,2025 r0 top locked
Q1 "2N7002KW" SOT-323 1215,1065 r0 top
Q2_PWR1 "BC856A-7-F" SOT-23 4605,1165 r0 top (schematic designator Q2)
Q2_PWR2 "BC856A-7-F" SOT-23 4605,95 r0 top (schematic designator Q2)
Q3_PWR1 "2N7002KW" SOT-323 3990,1205 r0 top (schematic designator Q3)
Q3_PWR2 "2N7002KW" SOT-323 3990,135 r0 top (schematic designator Q3)
Q4_PWR1 "2N7002KW" SOT-323 4280,1535 r270 top (schematic designator Q4)
Q4_PWR2 "2N7002KW" SOT-323 4280,465 r270 top (schematic designator Q4)
Q5_PWR1 "2N7002KW" SOT-323 4280,1800 r90 top (schematic designator Q5)
Q5_PWR2 "2N7002KW" SOT-323 4280,730 r90 top (schematic designator Q5)
R1_ADC1 "CRCW04026K65FKED" 0402 4210,1895 r180 top (schematic designator R1)
R1_ADC2 "CRCW04026K65FKED" 0402 4210,825 r180 top (schematic designator R1)
R2_ADC1 "CRCW0402261KFKED" 0402 3770,2040 r0 top (schematic designator R2)
R2_ADC2 "CRCW0402261KFKED" 0402 3770,970 r0 top (schematic designator R2)
R3_ADC1 "CRCW040247K0JNED" 0402 3770,1940 r180 top (schematic designator R3)
R3_ADC2 "CRCW040247K0JNED" 0402 3770,870 r180 top (schematic designator R3)
R4_ADC1 "CRCW0402576KFKED" 0402 4210,1940 r0 top (schematic designator R4)
R4_ADC2 "CRCW0402576KFKED" 0402 4210,870 r0 top (schematic designator R4)
R5_ADC1 "CRCW040247K0JNED" 0402 4210,1990 r0 top (schematic designator R5)
R5_ADC2 "CRCW040247K0JNED" 0402 4210,920 r0 top (schematic designator R5)
R6_ADC1 "CRCW0402340KFKED" 0402 4210,2090 r0 top (schematic designator R6)
R6_ADC2 "CRCW0402340KFKED" 0402 4210,1020 r0 top (schematic designator R6)
R7_ADC1 "CRCW04021K65FKED" 0402 3770,1990 r0 top (schematic designator R7)
R7_ADC2 "CRCW04021K65FKED" 0402 3770,920 r0 top (schematic designator R7)
R8_ADC1 "CRCW04028K25FKED" 0402 3770,2090 r180 top (schematic designator R8)
R8_ADC2 "CRCW04028K25FKED" 0402 3770,1020 r180 top (schematic designator R8)
R9_ADC1 "CRCW040247K0JNED" 0402 4210,2040 r180 top (schematic designator R9)
R9_ADC2 "CRCW040247K0JNED" 0402 4210,970 r180 top (schematic designator R9)
R10_ADC1 "CRCW040247K0JNED" 0402 5025,1980 r270 top (schematic designator R10)
R10_ADC2 "CRCW040247K0JNED" 0402 5025,910 r270 top (schematic designator R10)
R11_ADC1 "CRCW040247K0JNED" 0402 4380,2030 r270 top (schematic designator R11)
R11_ADC2 "CRCW040247K0JNED" 0402 4380,960 r270 top (schematic designator R11)
R12_ADC1 "CRCW04021K65FKED" 0402 5195,1355 r0 top (schematic designator R12)
R12_ADC2 "CRCW04021K65FKED" 0402 5195,285 r0 top (schematic designator R12)
R13_ADC1 "CRCW0402475RFKED" 0402 5755,2095 r0 top (schematic designator R13)
R13_ADC2 "CRCW0402475RFKED" 0402 5755,1025 r0 top (schematic designator R13)
R14_AFE1 "CRCW04025K11FKED" 0402 5450,1450 r180 top (schematic designator R14)
R14_AFE2 "CRCW04025K11FKED" 0402 5450,380 r180 top (schematic designator R14)
R15_AFE1 "CRCW040249R9FKED" 0402 5638.35,1165 r270 top (schematic designator R15)
R15_AFE2 "CRCW040249R9FKED" 0402 5638.35,95 r270 top (schematic designator R15)
R16_AFE1 "RNCF0603TKY4K99" 0603 5475,1525 r270 top (schematic designator R16)
R16_AFE2 "RNCF0603TKY4K99" 0603 5475,455 r270 top (schematic designator R16)
R17_AFE1 "CRCW04025K11FKED" 0402 5450,1600 r180 top (schematic designator R17)
R17_AFE2 "CRCW04025K11FKED" 0402 5450,530 r180 top (schematic designator R17)
R18_AFE1 "RN73C2A82K5BTDF" RN73_2A 5935,1470 r90 top (schematic designator R18)
R18_AFE2 "RN73C2A82K5BTDF" RN73_2A 5935,400 r90 top (schematic designator R18)
R19_AFE1 "RN73C2A17K8BTDF" RN73_2A 5800,1425 r0 top (schematic designator R19)
R19_AFE2 "RN73C2A17K8BTDF" RN73_2A 5800,355 r0 top (schematic designator R19)
R20_AFE1 "CRCW040249R9FKED" 0402 5583.35,1165 r270 top (schematic designator R20)
R20_AFE2 "CRCW040249R9FKED" 0402 5583.35,95 r270 top (schematic designator R20)
R21_AFE1 "CRCW04025K11FKED" 0402 5455,1685 r180 top (schematic designator R21)
R21_AFE2 "CRCW04025K11FKED" 0402 5455,615 r180 top (schematic designator R21)
R22_AFE1 "CRCW04025K11FKED" 0402 5455,1735 r180 top (schematic designator R22)
R22_AFE2 "CRCW04025K11FKED" 0402 5455,665 r180 top (schematic designator R22)
R23_AFE1 "CRCW040249R9FKED" 0402 5025,1880 r270 top (schematic designator R23)
R23_AFE2 "CRCW040249R9FKED" 0402 5025,810 r270 top (schematic designator R23)
R24_AFE1 "CRCW04025K11FKED" 0402 4838,1990 r270 top (schematic designator R24)
R24_AFE2 "CRCW04025K11FKED" 0402 4838,920 r270 top (schematic designator R24)
R25_AFE1 "RN73C2A27R4BTDF" RN73_2A 4863.21,2083.76 r180 top (schematic designator R25)
R25_AFE2 "RN73C2A27R4BTDF" RN73_2A 4863.21,1013.76 r180 top (schematic designator R25)
R26_AFE1 "CRCW04025K11FKED" 0402 4887,1990 r270 top (schematic designator R26)
R26_AFE2 "CRCW04025K11FKED" 0402 4887,920 r270 top (schematic designator R26)
R27_AFE1 "CRCW04025K11FKED" 0402 5115,1812.76 r180 top (schematic designator R27)
R27_AFE2 "CRCW04025K11FKED" 0402 5115,742.76 r180 top (schematic designator R27)
R28 "CRCW040247K0JNED" 0402 515,435 r0 top
R29 "CRCW040247K0JNED" 0402 735.02,715.01 r0 top
R30 "ERJ-3GEY0R00V" 0603 1135,1285 r180 top
R31 "ERJ-3GEY0R00V" 0603 1135,1210 r180 top
R32 "CRCW040247K0JNED" 0402 555,730 r270 top
R33 "CRCW040247K0JNED" 0402 735,355 r180 top
R34 "CRCW040247K0JNED" 0402 350.02,445.02 r90 top
R35 "CRCW040247K0JNED" 0402 425.02,445.01 r90 top
R36 "CRCW040247K0JNED" 0402 275.01,445.02 r90 top
R37 "CRCW04026K65FKED" 0402 200.01,445.02 r90 top
R38 "CRCW04026K65FKED" 0402 125.01,445.02 r90 top
R39 "CRCW040247K0JNED" 0402 1295,1065 r90 top
R40 "CRCW0402100KFKED" 0402 1160,1145 r180 top
R41 "CRCW0402261KFKED" 0402 1540,1060 r90 top
R42 "CRCW040247K0JNED" 0402 1135,1065 r90 top
R43 "CRCW0402200KFKED" 0402 1410,950 r270 top
R44 "CRCW04028K06FKED" 0402 1540,950 r90 top
R45 "CRCW04028K25FKED" 0402 920,935 r90 top
R46_PWR1 "CRCW120620R5FKEA" 1206 4475,1200 r270 top (schematic designator R46)
R46_PWR2 "CRCW120620R5FKEA" 1206 4475,130 r270 top (schematic designator R46)
R47_PWR1 "CRCW040247K0JNED" 0402 3995,1135 r0 top (schematic designator R47)
R47_PWR2 "CRCW040247K0JNED" 0402 3995,65 r0 top (schematic designator R47)
R48_PWR1 "CRCW0402953KFKED" 0402 4400,1155 r90 top (schematic designator R48)
R48_PWR2 "CRCW0402953KFKED" 0402 4400,85 r90 top (schematic designator R48)
R49_PWR1 "CRCW04025K11FKED" 0402 4590,1260 r0 top (schematic designator R49)
R49_PWR2 "CRCW04025K11FKED" 0402 4590,190 r0 top (schematic designator R49)
R50_PWR1 "CRCW04028K25FKED" 0402 4935,1195 r180 top (schematic designator R50)
R50_PWR2 "CRCW04028K25FKED" 0402 4935,125 r180 top (schematic designator R50)
R51_PWR1 "CRCW040247K0JNED" 0402 3995,1275 r180 top (schematic designator R51)
R51_PWR2 "CRCW040247K0JNED" 0402 3995,205 r180 top (schematic designator R51)
R52_PWR1 "CRCW0402953KFKED" 0402 4475,1330 r0 top (schematic designator R52)
R52_PWR2 "CRCW0402953KFKED" 0402 4475,260 r0 top (schematic designator R52)
R53_PWR1 "CRCW040247K0JNED" 0402 4400,1260 r270 top (schematic designator R53)
R53_PWR2 "CRCW040247K0JNED" 0402 4400,190 r270 top (schematic designator R53)
R54_PWR1 "CRCW0402931RFKED" 0402 4935,1240 r0 top (schematic designator R54)
R54_PWR2 "CRCW0402931RFKED" 0402 4935,170 r0 top (schematic designator R54)
R55_PWR1 "CRCW0402113KFKED" 0402 4060,1545 r270 top (schematic designator R55)
R55_PWR2 "CRCW0402113KFKED" 0402 4060,475 r270 top (schematic designator R55)
R56_PWR1 "CRCW0402100KFKED" 0402 4080,1615 r180 top (schematic designator R56)
R56_PWR2 "CRCW0402100KFKED" 0402 4080,545 r180 top (schematic designator R56)
R57_PWR1 "CRCW0402169KFKED" 0402 4110,1545 r270 top (schematic designator R57)
R57_PWR2 "CRCW0402169KFKED" 0402 4110,475 r270 top (schematic designator R57)
R58_PWR1 "CRCW040247K0JNED" 0402 4280,1610 r180 top (schematic designator R58)
R58_PWR2 "CRCW040247K0JNED" 0402 4280,540 r180 top (schematic designator R58)
R59_PWR1 "CRCW0402169KFKED" 0402 3015,1545 r0 top (schematic designator R59)
R59_PWR2 "CRCW0402169KFKED" 0402 3015,485 r0 top (schematic designator R59)
R60_PWR1 "CRCW0402113KFKED" 0402 4060,1760 r270 top (schematic designator R60)
R60_PWR2 "CRCW0402113KFKED" 0402 4060,690 r270 top (schematic designator R60)
R61_PWR1 "CRCW040247K0JNED" 0402 4280,1725 r0 top (schematic designator R61)
R61_PWR2 "CRCW040247K0JNED" 0402 4280,655 r0 top (schematic designator R61)
R62_PWR1 "CRCW04021R00JNED" 0402 2610,1875 r0 top (schematic designator R62)
R62_PWR2 "CRCW04021R00JNED" 0402 2610,805 r0 top (schematic designator R62)
R63_PWR1 "CRCW0402422KFKED" 0402 2805,1795 r180 top (schematic designator R63)
R63_PWR2 "CRCW0402422KFKED" 0402 2805,725 r180 top (schematic designator R63)
R64_PWR1 "CRCW0402100KFKED" 0402 2805,1750 r180 top (schematic designator R64)
R64_PWR2 "CRCW0402100KFKED" 0402 2805,680 r180 top (schematic designator R64)
R65_PWR1 "CRCW040254K9FKED" 0402 2785,1515 r270 top (schematic designator R65)
R65_PWR2 "CRCW040254K9FKED" 0402 2785,455 r270 top (schematic designator R65)
R66_PWR1 "CRCW040273K2FKED" 0402 4080,1835 r180 top (schematic designator R66)
R66_PWR2 "CRCW040273K2FKED" 0402 4080,765 r180 top (schematic designator R66)
R67_PWR1 "CRCW04028K66FKED" 0402 2805,1705 r0 top (schematic designator R67)
R67_PWR2 "CRCW04028K66FKED" 0402 2805,635 r0 top (schematic designator R67)
R68_PWR1 "CRCW04027K68FKED" 0402 2855,1540 r0 top (schematic designator R68)
R68_PWR2 "CRCW04027K68FKED" 0402 2855,480 r0 top (schematic designator R68)
R69_PWR1 "CRCW0402100KFKED" 0402 4110,1760 r90 top (schematic designator R69)
R69_PWR2 "CRCW0402100KFKED" 0402 4110,690 r90 top (schematic designator R69)
S1 "416131160802" SW_416131160802 255,285 r0 top
T1_PWR1 "750315856" Wurth_750315856 3380,1525 r0 top (schematic designator T1)
T1_PWR2 "750315856" Wurth_750315856 3380,455 r0 top (schematic designator T1)
TP1_ADC1 "TESTPOINT" TESTPOINT 5400,1315 r90 top (schematic designator TP1)
TP1_ADC2 "TESTPOINT" TESTPOINT 5400,970 r90 top (schematic designator TP1)
TP2 "TESTPOINT" TESTPOINT 1260,1260 r0 top
TP3 "TESTPOINT" TESTPOINT 2750,1075 r0 top
TP4_AFE1 "TESTPOINT" TESTPOINT 5400,1180 r90 top (schematic designator TP4)
TP4_AFE2 "TESTPOINT" TESTPOINT 5400,835 r90 top (schematic designator TP4)
TP5_AFE1 "TESTPOINT" TESTPOINT 3635,1845 r90 top (schematic designator TP5)
TP5_AFE2 "TESTPOINT" TESTPOINT 3635,775 r90 top (schematic designator TP5)
TP6_AFE1 "TESTPOINT" TESTPOINT 3525,1165 r90 top (schematic designator TP6)
TP6_AFE2 "TESTPOINT" TESTPOINT 3525,95 r90 top (schematic designator TP6)
TP7 "TESTPOINT" TESTPOINT 2600,1075 r0 top
TP8 "TESTPOINT" TESTPOINT 920,795 r0 top
TP10 "TESTPOINT" TESTPOINT 2900,1075 r0 top
U1_ADC1 "ISO7141CCDBQR" DBQ0016A_N 3380,2010.32 r0 top (schematic designator U1)
U1_ADC2 "ISO7141CCDBQR" DBQ0016A_N 3380,940.32 r0 top (schematic designator U1)
U2_ADC1 "LM2903PW" PW0008A_N 3995,2040 r180 top (schematic designator U2)
U2_ADC2 "LM2903PW" PW0008A_N 3995,970 r180 top (schematic designator U2)
U3_ADC1 "LMT01LPG" LPG0002A 5890,2085 r180 bottom (schematic designator U3)
U3_ADC2 "LMT01LPG" LPG0002A 5890,1015 r180 bottom (schematic designator U3)
U4_ADC1 "SN74LVC1G125DCKR" DCK0005A_N 3150,1960 r270 top (schematic designator U4)
U4_ADC2 "SN74LVC1G125DCKR" DCK0005A_N 3150,890 r270 top (schematic designator U4)
U5_ADC1 "SN74AHC594PWR" PW0016A_N 4550,2000 r180 top (schematic designator U5)
U5_ADC2 "SN74AHC594PWR" PW0016A_N 4550,930 r180 top (schematic designator U5)
U6_ADC1 "ADS1262IPWR" PW0028A_N 4975,1610 r0 top (schematic designator U6)
U6_ADC2 "ADS1262IPWR" PW0028A_N 4975,540 r0 top (schematic designator U6)
U7 "SN74LVC2G86DCTR" DCT0008A_N 540,570 r90 top
U8 "SN74LVC1G332DCKR" DCK0006A_N 735,615 r0 top
U9 "SN74LVC1G332DCKR" DCK0006A_N 735.02,455.02 r0 top
U10 "TPS61093DSKR" DSK0010A 1445,1075 r0 top
U11 "24LC256-I/ST" TSSOP-8 275,595 r180 top
U12_PWR1 "TPS7A4101DGNR" DGN0008B_N 4165,1200 r180 top (schematic designator U12)
U12_PWR2 "TPS7A4101DGNR" DGN0008B_N 4165,130 r180 top (schematic designator U12)
U13_PWR1 "TLV70433DBVT" DBV0005A_N 3935,1380 r90 top (schematic designator U13)
U13_PWR2 "TLV70433DBVT" DBV0005A_N 3935,310 r90 top (schematic designator U13)
U14_PWR1 "TPS7A4901DRBR" DRB0008A 3885,1560 r180 top (schematic designator U14)
U14_PWR2 "TPS7A4901DRBR" DRB0008A 3885,490 r180 top (schematic designator U14)
U15_PWR1 "LM5017SDX/NOPB" NGU0008B 2980,1720 r270 top (schematic designator U15)
U15_PWR2 "LM5017SDX/NOPB" NGU0008B 2980,660 r270 top (schematic designator U15)
U16_PWR1 "TPS7A3001DRBR" DRB0008A 3885,1775 r180 top (schematic designator U16)
U16_PWR2 "TPS7A3001DRBR" DRB0008A 3885,705 r180 top (schematic designator U16)
Y1_ADC1 "ECS-73-18-10X" ECS-3x10X 5070,1335 r0 top (schematic designator Y1)
Y1_ADC2 "ECS-73-18-10X" ECS-3x10X 5070,265 r0 top (schematic designator Y1)
ZZ1 "These assemblies are ESD sensitive, ESD precautions shall be observed." AssemblyNote 2792.09,5316 r90 top
ZZ2 "These assemblies must be clean and free from flux and all contaminants. Use of no clean flux is not acceptable." AssemblyNote 2612.09,5316 r90 top
ZZ3 "These assemblies must comply with workmanship standards IPC-A-610 Class 2, unless otherwise specified." AssemblyNote 2432.09,5316 r90 top

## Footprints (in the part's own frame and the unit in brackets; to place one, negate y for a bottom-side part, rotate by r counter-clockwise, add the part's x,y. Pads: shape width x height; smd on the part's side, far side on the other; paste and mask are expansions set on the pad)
0402 [mm] "0402 from SM-752 data"
  rect 0.8x0.6 smd: 1(-0.6,0) 2(0.6,0)
  silkscreen extent -1.22,-0.52 1.22,0.52, body extent -0.55,-0.3 0.55,0.3, height 0.6
0603 [mm] "0603 from SM-752 data"
  rect 1x0.95 smd: 1(-0.8,0) 2(0.8,0)
  silkscreen extent -1.52,-0.69 1.52,0.69, body extent -0.87,-0.47 0.87,0.47, height 1
0805_HV [mil] "0805 with 30mil clearance between pads"
  rect 50x63 smd: 1(-40,0) 2(40,0)
  silkscreen extent -74,-40 74,40, body extent -43,-29 43,29, height 57
1206 [mm] "1206 from SM-752 data"
  rect 1.3x1.85 smd: 1(-1.45,0) 2(1.45,0)
  silkscreen extent -2.4,-1.21 2.4,1.21, body extent -1.7,-0.9 1.7,0.9, height 1.35
1206_190 [mm] "1206_190"
  rect 1.1x1.6 smd: 1(-1.7,0) 2(1.7,0)
  silkscreen extent -0.9,-1 0.9,1, body extent -1.75,-0.95 1.75,0.95, height 1.9
AssemblyNote [mil] "Assembly Note"
DBQ0016A_N [mm] "SOP, 16-Leads, Body 4.9x3.9mm, Pitch 0.635mm, IPC Medium Density"
  oval 1.45x0.4 smd: 1(-2.725,2.222) 2(-2.725,1.587) 3(-2.725,0.953) 4(-2.725,0.318) 5(-2.725,-0.318) 6(-2.725,-0.953) 7(-2.725,-1.587) 8(-2.725,-2.222) 9(2.725,-2.222) 10(2.725,-1.587) 11(2.725,-0.953) 12(2.725,-0.318) 13(2.725,0.318) 14(2.725,0.953) 15(2.725,1.587) 16(2.725,2.222)
  silkscreen extent -3.35,-2.5 1.1,2.68, body extent -3.01,-2.45 3.01,2.45, height 1.63
DBV0005A_N [mm] "SOT23, 5-Leads, Body 2.9x1.6mm, Pitch 0.95mm, Lead Span 2.8mm, IPC Medium Density"
  rrect17% 1x0.6 smd: 1(-1.375,0.95) 2(-1.375,0) 3(-1.375,-0.95) 4(1.375,-0.95) 5(1.375,0.95)
  silkscreen extent -1.63,-1.55 0.38,1.55, body extent -1.42,-1.46 1.42,1.46, height 1.09
DCK0005A_N [mm] "SOT353, 5-Leads, Body 2x1.3mm, Pitch 0.65mm, Lead Span 2.1mm, IPC Medium Density"
  rrect25% 0.85x0.4 smd: 1(-1.125,0.65) 2(-1.125,0) 3(-1.125,-0.65) 4(1.125,-0.65) 5(1.125,0.65)
  silkscreen extent -1.48,-1.02 0.55,1.1, body extent -1.14,-1 1.14,1, height 0.95
DCK0006A_N [mm] "SOT23, 6-Leads, Body 2x1.3mm, Pitch 0.65mm, Lead Span 2.1mm, IPC Medium Density"
  rrect25% 0.85x0.4 smd: 1(-1.125,0.65) 2(-1.125,0) 3(-1.125,-0.65) 4(1.125,-0.65) 5(1.125,0) 6(1.125,0.65)
  silkscreen extent -1.5,-1.09 0.51,1.09, body extent -1.14,-1 1.14,1, height 0.95
DCT0008A_N [mm] "TSOP, 8-Leads, Body 3x2.8mm, Pitch 0.65mm, IPC Medium Density"
  oval 1.05x0.4 smd: 1(-1.975,0.975) 2(-1.975,0.325) 3(-1.975,-0.325) 4(-1.975,-0.975) 5(1.975,-0.975) 6(1.975,-0.325) 7(1.975,0.325) 8(1.975,0.975)
  silkscreen extent -2.32,-1.57 0.6,1.58, body extent -2.01,-1.47 2.01,1.48, height 1.3
DGN0008B_N [mm] "TSOP, 8-Leads, Body 3x3mm, Pitch 0.65mm, Thermal Pad 1.92x1.60mm, IPC Medium Density"
  rrect100% 1.35x0.45 smd: 1(-2.225,0.975) 2(-2.225,0.325) 3(-2.225,-0.325) 4(-2.225,-0.975) 5(2.225,-0.975) 6(2.225,-0.325) 7(2.225,0.325) 8(2.225,0.975)
  rrect5% 1.88x1.98 smd: 9(0,0)
  silkscreen extent -2.7,-1.55 0.95,1.55, body extent -2.46,-1.5 2.46,1.5, height 1.1
Diode_0603 [mm] "Based on Bourns recommended land pattern Rev 10/09"
  rect 0.7x1 smd: 1(-0.65,0) 2(0.65,0)
  silkscreen extent -1.5,-0.8 0.9,0.8, body extent -0.9,-0.5 0.9,0.5, height 0.85
DRB0008A [mm] "SON, 8-Leads, Body 3x3mm, Pitch 0.65mm, Thermal Pad 1.75x1.5mm, TI Recommended"
  rrect33% 0.6x0.3 smd: 1(-1.4,0.975) 2(-1.4,0.325) 3(-1.4,-0.325) 4(-1.4,-0.975) 5(1.4,-0.975) 6(1.4,-0.325) 7(1.4,0.325) 8(1.4,0.975)
  rrect7% 1.5x1.75 smd paste-0.75: 9(0,0)
  Top Layer region: -0.465,-1.5 -0.465,-0.875 -0.75,-0.875 -0.75,0.875 -0.465,0.875 -0.465,1.5 -0.185,1.5 -0.185,0.875 0.185,0.875 0.185,1.5 0.465,1.5 0.465,0.875 0.75,0.875 0.75,-0.875 0.465,-0.875 0.465,-1.5 0.185,-1.5 0.185,-0.875 -0.185,-0.875 -0.185,-1.5
  silkscreen extent -1.73,-1.73 1.73,1.73, body extent -1.57,-1.57 1.58,1.58, height 1.01
DSK0010A [mm] "SON, 10-Leads, Body 2.5x2.5mm, Pitch 0.5mm, Thermal Pad 2x1.2mm - ADI"
  oval 0.6x0.25 smd: 1(-1.15,1) 2(-1.15,0.5) 3(-1.15,0) 4(-1.15,-0.5) 5(-1.15,-1) 6(1.15,-1) 7(1.15,-0.5) 8(1.15,0) 9(1.15,0.5) 10(1.15,1)
  rect 1.2x2 smd paste-0.6: 11(0,0)
  silkscreen extent -1.3,-1.45 1.3,1.45, body extent -1.3,-1.3 1.3,1.3, height 0.81
ECS-3x10X [mm] "TH, 2-Leads, Dia 3.2mm"
  round 0.8 hole 0.5: 1(-0.55,0) 2(0.55,0)
  silkscreen extent -1.6,-1.6 1.6,1.6, body extent -1.6,-1.6 1.6,1.6, height 10.5
Fiducial10-20 [mm]
  round 1 smd mask+0.5: 1(0,0)
  Top Layer keep-out circle w1.178: c0,0 r0.5
"LB Q39G_BLUE" [mm] "OSRAM"
  rect 0.8x0.8 smd: 1(-0.75,0) 2(0.75,0)
  silkscreen extent 1.3,-0.5 1.52,0.5, body extent -0.85,-0.45 0.85,0.45, height 0.4
LPG0002A [mm] "TO, 2-Leads, Body 4x1.52mm"
  rrect9% 1.07x1.7 hole 0.75: 1(-1.27,0)
  rrect100% 1.07x1.7 hole 0.75: 2(1.27,0)
  round 0.75 hole 0.75 unplated paste+0 mask+0: MH(0,0)
  silkscreen extent -2.21,-1.25 2.21,1.25, body extent -2,-0.54 2,0.98, height 5.06
Major_BBB_SSHQ-123-D-08 [mm] "Female Connector, 2.54mm, 23x2, TH"
  rect 1.55x1.55 hole 1.02: 1(-27.94,-1.27)
  round 1.55 hole 1.02: 2(-27.94,1.27) 3(-25.4,-1.27) 4(-25.4,1.27) 5(-22.86,-1.27) 6(-22.86,1.27) 7(-20.32,-1.27) 8(-20.32,1.27) 9(-17.78,-1.27) 10(-17.78,1.27) 11(-15.24,-1.27) 12(-15.24,1.27) 13(-12.7,-1.27) 14(-12.7,1.27) 15(-10.16,-1.27) 16(-10.16,1.27) 17(-7.62,-1.27) 18(-7.62,1.27) 19(-5.08,-1.27) 20(-5.08,1.27) 21(-2.54,-1.27) 22(-2.54,1.27) 23(0,-1.27) 24(0,1.27) 25(2.54,-1.27) 26(2.54,1.27) 27(5.08,-1.27) 28(5.08,1.27) 29(7.62,-1.27) 30(7.62,1.27) 31(10.16,-1.27) 32(10.16,1.27) 33(12.7,-1.27) 34(12.7,1.27) 35(15.24,-1.27) 36(15.24,1.27) 37(17.78,-1.27) 38(17.78,1.27) 39(20.32,-1.27) 40(20.32,1.27) 41(22.86,-1.27) 42(22.86,1.27) 43(25.4,-1.27) 44(25.4,1.27) 45(27.94,-1.27) 46(27.94,1.27)
  silkscreen extent -29.53,-2.85 29.53,2.57, body extent -29.46,-2.51 29.46,2.51, height 8.51
MTGP_4-40_PanHead [mm] "4-40 Mounting Hole, Plated, for Pan Head"
  round 6.4 hole 3.5: 1(0,0)
NGU0008B [mm] "SON, 8-Leads, Body 4x4mm, Pitch 0.8mm"
  rrect33% 0.6x0.3 smd: 1(-1.9,1.2) 2(-1.9,0.4) 3(-1.9,-0.4) 4(-1.9,-1.2) 5(1.9,-1.2) 6(1.9,-0.4) 7(1.9,0.4) 8(1.9,1.2)
  rrect5% 1.98x3 smd paste-1.5: 9(0,0)
  silkscreen extent -2.15,-2.15 2.15,2.15, body extent -2.05,-2.05 2.05,2.05, height 0.81
Pb-Free_Overlay_Small [mil]
  silkscreen extent -46,-46 46,46
Phoenix_1844236 [mm] "Terminal Block, 4x1, 3.5mm, R/A, TH"
  rect 1.7x1.7 hole 1.2: 1(8,5.25)
  round 1.7 hole 1.2: 2(8,1.75) 3(8,-1.75) 4(8,-5.25)
  silkscreen extent 0.15,-7.7 9.75,7.7, body extent 0,-7.7 9.2,7.7, height 7.26
PhoenixContact_1803277 [mm] "Phoenix Contact"
  rect 1.8x1.8 hole 1.2: 1(-1.905,0)
  round 1.8 hole 1.2: 2(1.905,0)
  silkscreen extent -4.5,-8 4.51,1.6, body extent -4.5,-8 4.51,1.3, height 7.26
PW0008A_N [mm] "TSOP, 8-Leads, Body 3x4.4mm, Pitch 0.65mm, IPC Medium Density"
  oval 1.4x0.45 smd: 1(-2.95,0.975) 2(-2.95,0.325) 3(-2.95,-0.325) 4(-2.95,-0.975) 5(2.95,-0.975) 6(2.95,-0.325) 7(2.95,0.325) 8(2.95,0.975)
  silkscreen extent -3.4,-1.55 1.85,1.55, body extent -3.21,-1.5 3.21,1.5, height 1.2
PW0016A_N [mm] "TSOP, 16-Leads, Body 5x4.4mm, Pitch 0.65mm, IPC Medium Density"
  oval 1.4x0.45 smd: 1(-2.95,2.275) 2(-2.95,1.625) 3(-2.95,0.975) 4(-2.95,0.325) 5(-2.95,-0.325) 6(-2.95,-0.975) 7(-2.95,-1.625) 8(-2.95,-2.275) 9(2.95,-2.275) 10(2.95,-1.625) 11(2.95,-0.975) 12(2.95,-0.325) 13(2.95,0.325) 14(2.95,0.975) 15(2.95,1.625) 16(2.95,2.275)
  silkscreen extent -3.5,-2.55 1.85,2.75, body extent -3.21,-2.5 3.21,2.5, height 1
PW0028A_N [mm] "TSOP, 28-Leads, Body 9.7x4.4mm, Pitch 0.65mm, IPC Medium Density"
  oval 1.4x0.45 smd: 1(-2.95,4.225) 2(-2.95,3.575) 3(-2.95,2.925) 4(-2.95,2.275) 5(-2.95,1.625) 6(-2.95,0.975) 7(-2.95,0.325) 8(-2.95,-0.325) 9(-2.95,-0.975) 10(-2.95,-1.625) 11(-2.95,-2.275) 12(-2.95,-2.925) 13(-2.95,-3.575) 14(-2.95,-4.225) 15(2.95,-4.225) 16(2.95,-3.575) 17(2.95,-2.925) 18(2.95,-2.275) 19(2.95,-1.625) 20(2.95,-0.975) 21(2.95,-0.325) 22(2.95,0.325) 23(2.95,0.975) 24(2.95,1.625) 25(2.95,2.275) 26(2.95,2.925) 27(2.95,3.575) 28(2.95,4.225)
  silkscreen extent -3.5,-4.9 1.5,4.9, body extent -3.21,-4.85 3.21,4.85, height 1
RELAY_CPC1017N [mm] "SOP, 4-Lead, Body 4.089x3.81mm, Pitch 2.54mm"
  oval 1.3x0.6 smd: 1(-2.8,1.27) 2(-2.8,-1.27) 3(2.8,-1.27) 4(2.8,1.27)
  silkscreen extent -1.94,-2.15 1.94,2.4, body extent -1.94,-2.15 1.94,2.15, height 2.18
RN73_2A [mm] "TE Connectivity 0805"
  rect 1x1.45 smd: 1(-1,0) 2(1,0)
  silkscreen extent -1.85,-1 1.85,1, body extent -1.07,-0.7 1.07,0.7, height 0.65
